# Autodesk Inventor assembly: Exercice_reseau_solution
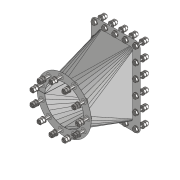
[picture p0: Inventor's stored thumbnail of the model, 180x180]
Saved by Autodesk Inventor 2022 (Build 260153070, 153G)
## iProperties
Created: 2021-07
Part Number: Exercice_reseau_solution
Document SubType Name: Construction soudée
Designer: Fabian
Weld Material: Aluminium 6061, soudé
Author: Fabian
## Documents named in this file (5)
- C:\Users\Fabian\Google Drive\01_Giup\01_Clients\07_ENI\Manuscrit\Fichiers_exercice\Chapitre_06\Exercice_reseau\Exercice_reseau_solution.iam
- C:\Users\Fabian\Google Drive\01_Giup\01_Clients\07_ENI\Manuscrit\Fichiers_exercice\Chapitre_06\Exercice_reseau\Bride_rect.ipt
- C:\Users\Fabian\Google Drive\01_Giup\01_Clients\07_ENI\Manuscrit\Fichiers_exercice\Chapitre_06\Exercice_reseau\Tremi.ipt
- C:\Users\Fabian\Google Drive\01_Giup\01_Clients\07_ENI\Manuscrit\Fichiers_exercice\Chapitre_06\Exercice_reseau\Bride_circ.ipt
- C:\Users\Fabian\Google Drive\01_Giup\01_Clients\07_ENI\Manuscrit\Fichiers_exercice\Chapitre_06\Exercice_reseau\Attache.iam
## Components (32 placed, 4 different names)
1. Bride_rect:1 — Logement:5
2. Tremi:1
3. Bride_circ:1 — Logement:4
4. Attache:2 [sub-assembly] — Logement:4
5. Attache:3 [sub-assembly]
6. Attache:4 [sub-assembly]
7. Attache:5 [sub-assembly]
8. Attache:6 [sub-assembly]
9. Attache:7 [sub-assembly]
10. Attache:8 [sub-assembly]
11. Attache:9 [sub-assembly]
12. Attache:10 [sub-assembly]
13. Attache:11 [sub-assembly]
14. Attache:12 [sub-assembly]
15. Attache:1 [sub-assembly] — Logement:5
16. Attache:13 [sub-assembly]
17. Attache:14 [sub-assembly]
18. Attache:15 [sub-assembly]
19. Attache:16 [sub-assembly]
20. Attache:17 [sub-assembly]
21. Attache:21 [sub-assembly]
22. Attache:22 [sub-assembly]
23. Attache:26 [sub-assembly]
24. Attache:27 [sub-assembly]
25. Attache:31 [sub-assembly]
26. Attache:32 [sub-assembly]
27. Attache:36 [sub-assembly]
28. Attache:37 [sub-assembly]
29. Attache:38 [sub-assembly]
30. Attache:39 [sub-assembly]
31. Attache:40 [sub-assembly]
32. Attache:41 [sub-assembly]
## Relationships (2: Insert 2)
- Logement:4 [Insert]: Bride_circ:1 ↔ Attache:2
- Logement:5 [Insert]: Bride_rect:1 ↔ Attache:1
